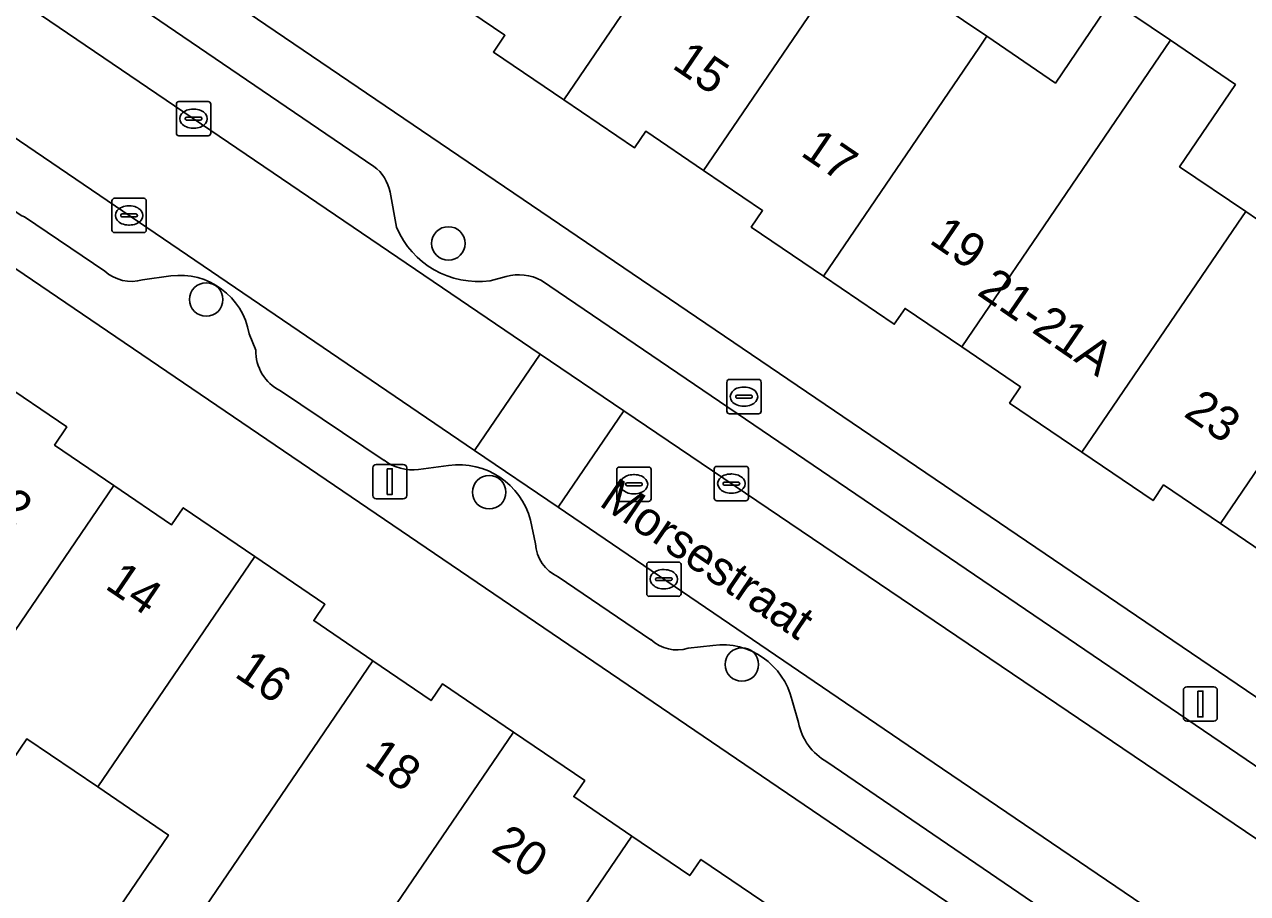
# Model space of a CAD drawing. Extents: x 159279 to 160377, y 384531 to 385888.
# Drawn here: x 159870.14 to 159905.8, y 384790.68 to 384816.01 of the extents above; entities that cross this region are included whole.
import ezdxf

# ---------------------------------------------------------------- set-up
doc = ezdxf.new("R2010")
doc.units = 0
for name, color, linetype in [('IMGEO_Boom', 7, 'Continuous'), ('IMGEO_Brandkraan', 7, 'Continuous'), ('IMGEO_Erf', 7, 'Continuous'), ('IMGEO_Kolk', 7, 'Continuous'), ('IMGEO_Lichtmast', 7, 'Continuous'), ('IMGEO_Openbare_ruimte_label', 7, 'Continuous'), ('IMGEO_Pand', 7, 'Continuous'), ('IMGEO_Pand_nummerreeks', 7, 'Continuous'), ('IMGEO_Parkeervlak_open', 7, 'Continuous'), ('IMGEO_Rijbaan_lokaal_open', 7, 'Continuous'), ('IMGEO_Rioolput', 7, 'Continuous'), ('IMGEO_Voetpad_open', 7, 'Continuous')]:
    doc.layers.add(name, color=color, linetype=linetype)

msp = doc.modelspace()

# ---------------------------------------------------------------- linework, layer by layer
at = {"layer": 'IMGEO_Boom'}
for centre in [(159882.498, 384809.63), (159875.436, 384807.995), (159883.686, 384802.377), (159891.055, 384797.353)]:
    msp.add_circle(centre, 0.489, dxfattribs=at)
at = {"layer": 'IMGEO_Brandkraan'}
for p, q in [((159890.616, 384804.738), (159890.616, 384805.59)), ((159890.691, 384805.664), (159891.543, 384805.664)), ((159891.617, 384805.59), (159891.617, 384804.738)), ((159890.875, 384805.158), (159890.875, 384805.17)), ((159891.313, 384805.121), (159890.915, 384805.121)), ((159890.918, 384805.207), (159891.316, 384805.207)), ((159891.104, 384805.444), (159891.129, 384805.444)), ((159891.359, 384805.17), (159891.359, 384805.158)), ((159891.127, 384804.884), (159891.102, 384804.884)), ((159891.543, 384804.664), (159890.691, 384804.664))]:
    msp.add_line(p, q, dxfattribs=at)
for points in [[(159890.616, 384804.738), (159890.616, 384805.59)], [(159890.691, 384805.664), (159891.543, 384805.664)], [(159891.617, 384805.59), (159891.617, 384804.738)], [(159891.543, 384804.664), (159890.691, 384804.664)]]:
    msp.add_lwpolyline(points, dxfattribs=at)
for centre, radius, start, end in [((159890.693, 384805.588), 0.0765, 91.552, 178.448), ((159890.693, 384805.588), 0.0765, 91.552, 178.448), ((159891.541, 384805.588), 0.0765, 1.552, 88.448), ((159891.541, 384805.588), 0.0765, 1.552, 88.448), ((159890.915, 384805.167), 0.0403, 85.8775, 175.7526), ((159890.912, 384805.157), 0.0366, 178.938, 274.7102), ((159891.316, 384805.164), 0.043, 264.8664, 352.4533), ((159891.32, 384805.169), 0.0386, 1.7309, 96.639), ((159890.693, 384804.74), 0.0765, 181.552, 268.448), ((159890.693, 384804.74), 0.0765, 181.552, 268.448), ((159891.541, 384804.74), 0.0765, 271.552, 358.448), ((159891.541, 384804.74), 0.0765, 271.552, 358.448)]:
    msp.add_arc(centre, radius, start, end, dxfattribs=at)
for centre, major_axis, ratio, start_param, end_param in [((159891.103, 384805.164), (-0.387, 0.002), 0.722429, 4.712389, 7.853982), ((159891.128, 384805.164), (-0.39, 0.002), 0.717154, 1.570796, 4.712389)]:
    msp.add_ellipse(centre, major_axis=major_axis, ratio=ratio, start_param=start_param, end_param=end_param, dxfattribs=at)
at = {"layer": 'IMGEO_Erf'}
for points in [[(159857.677, 384829.243), (159933.27, 384777.928)], [(159927.578, 384769.66), (159852.026, 384821.042)], [(159896.183, 384817.035), (159898.193, 384815.669), (159900.198, 384814.306), (159901.837, 384816.717), (159903.548, 384815.554), (159905.445, 384814.264), (159903.817, 384811.868), (159905.747, 384810.557), (159907.451, 384809.398)], [(159906.712, 384800.308), (159905.008, 384801.466), (159903.352, 384802.591), (159903.043, 384802.135), (159900.968, 384803.545), (159898.862, 384804.977), (159899.182, 384805.446), (159897.464, 384806.614), (159895.813, 384807.736), (159895.498, 384807.273), (159893.434, 384808.676), (159891.329, 384810.106), (159891.657, 384810.588), (159889.939, 384811.756), (159888.252, 384812.903), (159887.922, 384812.417), (159885.866, 384813.814), (159883.812, 384815.21), (159884.145, 384815.699), (159882.458, 384816.846)], [(159869.335, 384805.667), (159871.372, 384804.279), (159871.013, 384803.752), (159872.744, 384802.573), (159874.429, 384801.426), (159874.768, 384801.924), (159876.853, 384800.504), (159878.898, 384799.112), (159878.571, 384798.632), (159880.295, 384797.458), (159881.995, 384796.3), (159882.33, 384796.792), (159884.398, 384795.384), (159886.472, 384793.971), (159886.152, 384793.501), (159887.847, 384792.347), (159889.535, 384791.197), (159889.859, 384791.672), (159891.94, 384790.255)], [(159871.515, 384788.242), (159874.333, 384792.38), (159872.274, 384793.782), (159870.211, 384795.187), (159867.425, 384791.096)]]:
    msp.add_lwpolyline(points, dxfattribs=at)
at = {"layer": 'IMGEO_Kolk'}
for p, q in [((159874.567, 384812.842), (159874.567, 384813.694)), ((159874.642, 384813.768), (159875.494, 384813.768)), ((159875.568, 384813.694), (159875.568, 384812.842)), ((159874.869, 384813.311), (159875.267, 384813.311)), ((159875.055, 384813.548), (159875.08, 384813.548)), ((159874.826, 384813.262), (159874.826, 384813.274)), ((159875.264, 384813.225), (159874.866, 384813.225)), ((159875.078, 384812.988), (159875.053, 384812.988)), ((159875.31, 384813.274), (159875.31, 384813.262)), ((159875.494, 384812.768), (159874.642, 384812.768)), ((159872.688, 384810.02), (159872.688, 384810.872)), ((159872.763, 384810.946), (159873.615, 384810.946)), ((159873.689, 384810.872), (159873.689, 384810.02)), ((159872.99, 384810.489), (159873.388, 384810.489)), ((159873.176, 384810.726), (159873.201, 384810.726)), ((159872.947, 384810.44), (159872.947, 384810.452)), ((159873.385, 384810.403), (159872.987, 384810.403)), ((159873.199, 384810.166), (159873.174, 384810.166)), ((159873.431, 384810.452), (159873.431, 384810.44)), ((159873.615, 384809.946), (159872.763, 384809.946)), ((159890.248, 384802.202), (159890.248, 384803.054)), ((159890.323, 384803.128), (159891.175, 384803.128)), ((159891.249, 384803.054), (159891.249, 384802.202)), ((159890.507, 384802.622), (159890.507, 384802.634)), ((159890.55, 384802.671), (159890.948, 384802.671)), ((159890.736, 384802.908), (159890.761, 384802.908)), ((159890.991, 384802.634), (159890.991, 384802.622)), ((159890.945, 384802.585), (159890.547, 384802.585)), ((159890.759, 384802.348), (159890.734, 384802.348)), ((159891.175, 384802.128), (159890.323, 384802.128)), ((159888.28, 384799.415), (159888.28, 384800.267)), ((159888.355, 384800.341), (159889.207, 384800.341)), ((159888.768, 384800.121), (159888.793, 384800.121)), ((159889.281, 384800.267), (159889.281, 384799.415)), ((159888.539, 384799.835), (159888.539, 384799.847)), ((159888.977, 384799.798), (159888.579, 384799.798)), ((159888.582, 384799.884), (159888.98, 384799.884)), ((159889.023, 384799.847), (159889.023, 384799.835)), ((159888.791, 384799.561), (159888.766, 384799.561)), ((159889.207, 384799.341), (159888.355, 384799.341))]:
    msp.add_line(p, q, dxfattribs=at)
for points in [[(159874.567, 384812.842), (159874.567, 384813.694)], [(159874.642, 384813.768), (159875.494, 384813.768)], [(159875.568, 384813.694), (159875.568, 384812.842)], [(159875.494, 384812.768), (159874.642, 384812.768)], [(159872.688, 384810.02), (159872.688, 384810.872)], [(159872.763, 384810.946), (159873.615, 384810.946)], [(159873.689, 384810.872), (159873.689, 384810.02)], [(159873.615, 384809.946), (159872.763, 384809.946)], [(159890.248, 384802.202), (159890.248, 384803.054)], [(159890.323, 384803.128), (159891.175, 384803.128)], [(159891.249, 384803.054), (159891.249, 384802.202)], [(159891.175, 384802.128), (159890.323, 384802.128)], [(159888.28, 384799.415), (159888.28, 384800.267)], [(159888.355, 384800.341), (159889.207, 384800.341)], [(159889.281, 384800.267), (159889.281, 384799.415)], [(159889.207, 384799.341), (159888.355, 384799.341)]]:
    msp.add_lwpolyline(points, dxfattribs=at)
for centre, radius, start, end in [((159874.644, 384813.692), 0.0765, 91.552, 178.448), ((159874.644, 384813.692), 0.0765, 91.552, 178.448), ((159875.492, 384813.692), 0.0765, 1.552, 88.448), ((159875.492, 384813.692), 0.0765, 1.552, 88.448), ((159874.866, 384813.271), 0.0403, 85.8775, 175.7526), ((159875.271, 384813.273), 0.0386, 1.7309, 96.639), ((159874.863, 384813.261), 0.0366, 178.938, 274.7102), ((159875.267, 384813.268), 0.043, 264.8664, 352.4533), ((159874.644, 384812.844), 0.0765, 181.552, 268.448), ((159874.644, 384812.844), 0.0765, 181.552, 268.448), ((159875.492, 384812.844), 0.0765, 271.552, 358.448), ((159875.492, 384812.844), 0.0765, 271.552, 358.448), ((159872.765, 384810.87), 0.0765, 91.552, 178.448), ((159872.765, 384810.87), 0.0765, 91.552, 178.448), ((159873.613, 384810.87), 0.0765, 1.552, 88.448), ((159873.613, 384810.87), 0.0765, 1.552, 88.448), ((159872.987, 384810.449), 0.0403, 85.8775, 175.7526), ((159873.392, 384810.451), 0.0386, 1.7309, 96.639), ((159872.984, 384810.439), 0.0366, 178.938, 274.7102), ((159873.388, 384810.446), 0.043, 264.8664, 352.4533), ((159872.765, 384810.022), 0.0765, 181.552, 268.448), ((159872.765, 384810.022), 0.0765, 181.552, 268.448), ((159873.613, 384810.022), 0.0765, 271.552, 358.448), ((159873.613, 384810.022), 0.0765, 271.552, 358.448), ((159890.325, 384803.052), 0.0765, 91.552, 178.448), ((159890.325, 384803.052), 0.0765, 91.552, 178.448), ((159891.173, 384803.052), 0.0765, 1.552, 88.448), ((159891.173, 384803.052), 0.0765, 1.552, 88.448), ((159890.547, 384802.631), 0.0403, 85.8775, 175.7526), ((159890.544, 384802.621), 0.0366, 178.938, 274.7102), ((159890.948, 384802.628), 0.043, 264.8664, 352.4533), ((159890.952, 384802.633), 0.0386, 1.7309, 96.639), ((159890.325, 384802.204), 0.0765, 181.552, 268.448), ((159890.325, 384802.204), 0.0765, 181.552, 268.448), ((159891.173, 384802.204), 0.0765, 271.552, 358.448), ((159891.173, 384802.204), 0.0765, 271.552, 358.448), ((159888.357, 384800.265), 0.0765, 91.552, 178.448), ((159888.357, 384800.265), 0.0765, 91.552, 178.448), ((159889.205, 384800.265), 0.0765, 1.552, 88.448), ((159889.205, 384800.265), 0.0765, 1.552, 88.448), ((159888.579, 384799.844), 0.0403, 85.8775, 175.7526), ((159888.576, 384799.834), 0.0366, 178.938, 274.7102), ((159888.98, 384799.841), 0.043, 264.8664, 352.4533), ((159888.984, 384799.846), 0.0386, 1.7309, 96.639), ((159888.357, 384799.417), 0.0765, 181.552, 268.448), ((159888.357, 384799.417), 0.0765, 181.552, 268.448), ((159889.205, 384799.417), 0.0765, 271.552, 358.448), ((159889.205, 384799.417), 0.0765, 271.552, 358.448)]:
    msp.add_arc(centre, radius, start, end, dxfattribs=at)
for centre, major_axis, ratio, start_param, end_param in [((159875.054, 384813.268), (-0.387, 0.002), 0.722429, 4.712389, 7.853982), ((159875.079, 384813.268), (-0.39, 0.002), 0.717154, 1.570796, 4.712389), ((159873.175, 384810.446), (-0.387, 0.002), 0.722429, 4.712389, 7.853982), ((159873.2, 384810.446), (-0.39, 0.002), 0.717154, 1.570796, 4.712389), ((159890.735, 384802.628), (-0.387, 0.002), 0.722429, 4.712389, 7.853982), ((159890.76, 384802.628), (-0.39, 0.002), 0.717154, 1.570796, 4.712389), ((159888.767, 384799.841), (-0.387, 0.002), 0.722429, 4.712389, 7.853982), ((159888.792, 384799.841), (-0.39, 0.002), 0.717154, 1.570796, 4.712389)]:
    msp.add_ellipse(centre, major_axis=major_axis, ratio=ratio, start_param=start_param, end_param=end_param, dxfattribs=at)
at = {"layer": 'IMGEO_Lichtmast'}
for p, q in [((159880.293, 384802.285), (159880.293, 384803.085)), ((159880.293, 384803.085), (159880.293, 384802.285)), ((159880.393, 384803.185), (159881.183, 384803.185)), ((159881.183, 384803.185), (159880.393, 384803.185)), ((159881.283, 384803.085), (159881.283, 384802.285)), ((159881.283, 384802.285), (159881.283, 384803.085)), ((159881.183, 384802.185), (159880.393, 384802.185)), ((159880.393, 384802.185), (159881.183, 384802.185)), ((159903.927, 384795.801), (159903.927, 384796.601)), ((159903.927, 384796.601), (159903.927, 384795.801)), ((159904.027, 384796.701), (159904.817, 384796.701)), ((159904.817, 384796.701), (159904.027, 384796.701)), ((159904.917, 384796.601), (159904.917, 384795.801)), ((159904.917, 384795.801), (159904.917, 384796.601)), ((159904.817, 384795.701), (159904.027, 384795.701)), ((159904.027, 384795.701), (159904.817, 384795.701))]:
    msp.add_line(p, q, dxfattribs=at)
for points in [[(159880.713, 384803.06), (159880.863, 384803.06), (159880.863, 384802.31), (159880.713, 384802.31), (159880.713, 384803.06)], [(159904.347, 384796.576), (159904.497, 384796.576), (159904.497, 384795.826), (159904.347, 384795.826), (159904.347, 384796.576)]]:
    msp.add_lwpolyline(points, dxfattribs=at)
for centre, start, end in [((159880.393, 384803.085), 90, 180), ((159880.393, 384803.085), 90, 180), ((159881.183, 384803.085), 0, 90), ((159881.183, 384803.085), 360, 90), ((159880.393, 384802.285), 180, 270), ((159880.393, 384802.285), 180, 270), ((159881.183, 384802.285), 270, 0), ((159881.183, 384802.285), 270, 0), ((159904.027, 384796.601), 90, 180), ((159904.027, 384796.601), 90, 180), ((159904.817, 384796.601), 0, 90), ((159904.817, 384796.601), 360, 90), ((159904.027, 384795.801), 180, 270), ((159904.027, 384795.801), 180, 270), ((159904.817, 384795.801), 270, 0), ((159904.817, 384795.801), 270, 0)]:
    msp.add_arc(centre, 0.1, start, end, dxfattribs=at)
at = {"layer": 'IMGEO_Pand'}
for points in [[(159892.175, 384823.123), (159890.141, 384824.506), (159893.232, 384829.055), (159893.069, 384829.166), (159891.286, 384830.378), (159891.221, 384830.28), (159889.322, 384827.386), (159889.51, 384827.262), (159888.511, 384825.74), (159882.458, 384816.846), (159884.145, 384815.699), (159883.812, 384815.21), (159885.866, 384813.814), (159890.417, 384820.5), (159890.647, 384820.837)], [(159896.035, 384820.715), (159896.794, 384821.831), (159897.628, 384823.101), (159895.864, 384824.258), (159894.387, 384822.007), (159892.343, 384823.374), (159892.175, 384823.123), (159890.647, 384820.837), (159890.417, 384820.5), (159885.866, 384813.814), (159887.922, 384812.417), (159888.252, 384812.903), (159889.939, 384811.756)], [(159897.846, 384819.483), (159898.605, 384820.601), (159896.794, 384821.831), (159896.035, 384820.715), (159889.939, 384811.756), (159891.657, 384810.588), (159891.329, 384810.106), (159893.434, 384808.676), (159897.979, 384815.354), (159898.193, 384815.669), (159896.183, 384817.035)], [(159893.434, 384808.676), (159895.498, 384807.273), (159895.813, 384807.736), (159897.464, 384806.614), (159903.548, 384815.554), (159901.837, 384816.717), (159900.198, 384814.306), (159898.193, 384815.669), (159897.979, 384815.354)], [(159905.514, 384810.225), (159905.747, 384810.557), (159903.817, 384811.868), (159905.445, 384814.264), (159903.548, 384815.554), (159897.464, 384806.614), (159899.182, 384805.446), (159898.862, 384804.977), (159900.968, 384803.545)], [(159911.113, 384810.437), (159911.848, 384811.527), (159913.079, 384813.295), (159911.041, 384814.68), (159907.451, 384809.398), (159905.747, 384810.557), (159905.514, 384810.225), (159900.968, 384803.545), (159903.043, 384802.135), (159903.352, 384802.591), (159905.008, 384801.466)], [(159911.199, 384806.878), (159912.827, 384809.272), (159915.083, 384812.59), (159913.39, 384813.742), (159913.079, 384813.295), (159911.848, 384811.527), (159911.113, 384810.437), (159905.008, 384801.466), (159906.712, 384800.308), (159906.391, 384799.836), (159908.595, 384798.339), (159913.148, 384805.031), (159913.39, 384805.388)], [(159872.744, 384802.573), (159871.013, 384803.752), (159871.372, 384804.279), (159869.335, 384805.667), (159864.738, 384798.918), (159866.866, 384797.469), (159864.078, 384793.375), (159865.719, 384792.257)], [(159865.719, 384792.257), (159867.425, 384791.096), (159870.211, 384795.187), (159872.274, 384793.782), (159876.853, 384800.504), (159874.768, 384801.924), (159874.429, 384801.426), (159872.744, 384802.573)], [(159880.295, 384797.458), (159878.571, 384798.632), (159878.898, 384799.112), (159876.853, 384800.504), (159872.274, 384793.782), (159874.333, 384792.38), (159871.515, 384788.242), (159873.093, 384787.167), (159873.225, 384787.078)], [(159884.398, 384795.384), (159882.33, 384796.792), (159881.995, 384796.3), (159880.295, 384797.458), (159873.225, 384787.078), (159874.799, 384786.006), (159875.897, 384787.618), (159878.115, 384786.14), (159879.822, 384788.664)], [(159887.847, 384792.347), (159886.152, 384793.501), (159886.472, 384793.971), (159884.398, 384795.384), (159879.822, 384788.664), (159878.115, 384786.14), (159880.107, 384784.813), (159879.015, 384783.209), (159880.797, 384781.995)], [(159891.94, 384790.255), (159889.859, 384791.672), (159889.535, 384791.197), (159887.847, 384792.347), (159880.797, 384781.995), (159882.488, 384780.844), (159883.44, 384782.242), (159885.518, 384780.826), (159887.372, 384783.548)]]:
    msp.add_lwpolyline(points, close=True, dxfattribs=at)
at = {"layer": 'IMGEO_Parkeervlak_open'}
for points in [[(159841.061, 384836.342), (159869.05, 384817.352), (159885.17, 384806.406), (159887.611, 384804.749), (159908.324, 384790.738), (159926.959, 384778.09), (159945.396, 384765.37), (159945.552, 384765.562)], [(159943.334, 384762.401), (159943.479, 384762.606), (159926.868, 384773.971), (159896.121, 384794.85), (159885.702, 384801.937), (159883.263, 384803.596), (159866.73, 384814.841), (159839.216, 384833.593)], [(159880.327, 384811.876), (159859.008, 384826.382)], [(159880.985, 384810.1), (159880.796, 384811.121)], [(159870.137, 384810.402), (159872.483, 384808.821)], [(159873.579, 384808.57), (159874.403, 384808.682)], [(159884.181, 384808.664), (159883.713, 384808.543)], [(159918.388, 384786.002), (159885.211, 384808.551)], [(159876.686, 384806.999), (159876.884, 384806.519)], [(159877.598, 384805.335), (159880.623, 384803.306)], [(159881.63, 384803.04), (159882.505, 384803.154)], [(159884.889, 384801.56), (159885.038, 384800.876)], [(159885.699, 384799.907), (159888.404, 384798.077)], [(159889.487, 384797.825), (159890.209, 384797.911)], [(159892.517, 384796.304), (159892.704, 384795.659)], [(159893.533, 384794.514), (159901.391, 384789.147)]]:
    msp.add_lwpolyline(points, dxfattribs=at)
for centre, radius, start, end in [((159879.592, 384810.896), 1.225, 10.5702, 53.1262), ((159870.521, 384811.357), 1.029, 172.7943, 248.086), ((159883.367, 384811.106), 2.586, 202.8873, 277.6818), ((159873.254, 384809.67), 1.147, 227.7469, 286.4548), ((159874.671, 384806.656), 2.044, 9.6619, 97.5438), ((159884.557, 384807.338), 1.378, 61.6553, 105.8231), ((159878.161, 384806.482), 1.277, 178.328, 243.8554), ((159881.459, 384804.432), 1.402, 233.4008, 277.0056), ((159882.805, 384801.023), 2.152, 14.4562, 98.0085), ((159886.188, 384800.95), 1.152, 183.6976, 244.9018), ((159889.169, 384798.912), 1.132, 227.4929, 286.3093), ((159890.474, 384795.831), 2.097, 13.04, 97.2631), ((159894.371, 384795.993), 1.7, 191.3347, 240.4757)]:
    msp.add_arc(centre, radius, start, end, dxfattribs=at)
at = {"layer": 'IMGEO_Rijbaan_lokaal_open'}
for points in [[(159885.17, 384806.406), (159869.05, 384817.352), (159841.061, 384836.342), (159840.702, 384836.586), (159838.838, 384833.851), (159839.216, 384833.593), (159866.73, 384814.841), (159883.263, 384803.596)], [(159885.17, 384806.406), (159883.263, 384803.596), (159885.702, 384801.937), (159887.611, 384804.749)], [(159926.959, 384778.09), (159908.324, 384790.738), (159887.611, 384804.749), (159885.702, 384801.937), (159896.121, 384794.85), (159926.868, 384773.971), (159943.479, 384762.606), (159945.396, 384765.37)]]:
    msp.add_lwpolyline(points, close=True, dxfattribs=at)
at = {"layer": 'IMGEO_Rioolput'}
for p, q in [((159887.407, 384802.184), (159887.407, 384803.036)), ((159887.482, 384803.11), (159888.334, 384803.11)), ((159888.408, 384803.036), (159888.408, 384802.184)), ((159887.666, 384802.604), (159887.666, 384802.616)), ((159887.709, 384802.653), (159888.107, 384802.653)), ((159887.895, 384802.89), (159887.92, 384802.89)), ((159888.15, 384802.616), (159888.15, 384802.604)), ((159888.104, 384802.567), (159887.706, 384802.567)), ((159887.918, 384802.33), (159887.893, 384802.33)), ((159888.334, 384802.11), (159887.482, 384802.11))]:
    msp.add_line(p, q, dxfattribs=at)
for points in [[(159887.407, 384802.184), (159887.407, 384803.036)], [(159887.482, 384803.11), (159888.334, 384803.11)], [(159888.408, 384803.036), (159888.408, 384802.184)], [(159888.334, 384802.11), (159887.482, 384802.11)]]:
    msp.add_lwpolyline(points, dxfattribs=at)
for centre, radius, start, end in [((159887.484, 384803.034), 0.0765, 91.552, 178.448), ((159887.484, 384803.034), 0.0765, 91.552, 178.448), ((159888.332, 384803.034), 0.0765, 1.552, 88.448), ((159888.332, 384803.034), 0.0765, 1.552, 88.448), ((159887.706, 384802.613), 0.0403, 85.8775, 175.7526), ((159888.111, 384802.615), 0.0386, 1.7309, 96.639), ((159887.703, 384802.603), 0.0366, 178.938, 274.7102), ((159888.107, 384802.61), 0.043, 264.8664, 352.4533), ((159887.484, 384802.186), 0.0765, 181.552, 268.448), ((159887.484, 384802.186), 0.0765, 181.552, 268.448), ((159888.332, 384802.186), 0.0765, 271.552, 358.448), ((159888.332, 384802.186), 0.0765, 271.552, 358.448)]:
    msp.add_arc(centre, radius, start, end, dxfattribs=at)
for centre, major_axis, ratio, start_param, end_param in [((159887.894, 384802.61), (-0.387, 0.002), 0.722429, 4.712389, 7.853982), ((159887.919, 384802.61), (-0.39, 0.002), 0.717154, 1.570796, 4.712389)]:
    msp.add_ellipse(centre, major_axis=major_axis, ratio=ratio, start_param=start_param, end_param=end_param, dxfattribs=at)
at = {"layer": 'IMGEO_Voetpad_open'}
for points in [[(159839.216, 384833.593), (159838.838, 384833.851), (159838.334, 384834.194), (159838.015, 384834.391), (159837.68, 384834.559), (159835.991, 384831.945), (159843.603, 384826.792), (159848.594, 384823.395), (159851.246, 384821.574), (159852.026, 384821.042), (159927.578, 384769.66), (159928.216, 384769.226), (159928.533, 384769.015), (159941.948, 384760.067), (159943.396, 384762.244), (159943.334, 384762.401)], [(159945.552, 384765.562), (159947.447, 384768.384), (159942.761, 384771.531), (159933.683, 384777.648), (159933.27, 384777.928), (159857.677, 384829.243)], [(159859.008, 384826.382), (159880.327, 384811.876)], [(159880.796, 384811.121), (159880.985, 384810.1)], [(159872.483, 384808.821), (159870.137, 384810.402)], [(159874.403, 384808.682), (159873.579, 384808.57)], [(159883.713, 384808.543), (159884.181, 384808.664)], [(159885.211, 384808.551), (159918.388, 384786.002)], [(159876.884, 384806.519), (159876.686, 384806.999)], [(159880.623, 384803.306), (159877.598, 384805.335)], [(159882.505, 384803.154), (159881.63, 384803.04)], [(159885.038, 384800.876), (159884.889, 384801.56)], [(159888.404, 384798.077), (159885.699, 384799.907)], [(159890.209, 384797.911), (159889.487, 384797.825)], [(159892.704, 384795.659), (159892.517, 384796.304)], [(159901.391, 384789.147), (159893.533, 384794.514)]]:
    msp.add_lwpolyline(points, dxfattribs=at)
for centre, radius, start, end in [((159879.592, 384810.896), 1.225, 10.5702, 53.1262), ((159870.521, 384811.357), 1.029, 172.7943, 248.086), ((159883.367, 384811.106), 2.586, 202.8873, 277.6818), ((159873.254, 384809.67), 1.147, 227.7469, 286.4548), ((159874.671, 384806.656), 2.044, 9.6619, 97.5438), ((159884.557, 384807.338), 1.378, 61.6553, 105.8231), ((159878.161, 384806.482), 1.277, 178.328, 243.8554), ((159881.459, 384804.432), 1.402, 233.4008, 277.0056), ((159882.805, 384801.023), 2.152, 14.4562, 98.0085), ((159886.188, 384800.95), 1.152, 183.6976, 244.9018), ((159889.169, 384798.912), 1.132, 227.4929, 286.3093), ((159890.474, 384795.831), 2.097, 13.04, 97.2631), ((159894.371, 384795.993), 1.7, 191.3347, 240.4757)]:
    msp.add_arc(centre, radius, start, end, dxfattribs=at)

# ---------------------------------------------------------------- texts
at = {"layer": 'IMGEO_Openbare_ruimte_label'}
msp.add_text('Morsestraat', height=1, rotation=325.8014, dxfattribs=at).set_placement((159886.856, 384802.01))
at = {"layer": 'IMGEO_Pand_nummerreeks'}
for s, rotation, p in [('15', 325.76, (159888.985, 384814.766)), ('17', 325.759, (159892.733, 384812.214)), ('19', 325.759, (159896.482, 384809.663)), ('21-21A', 325.5939, (159897.88, 384808.156)), ('23', 325.76, (159903.904, 384804.611)), ('12', 325.7429, (159868.673, 384802.165)), ('14', 325.7429, (159872.451, 384799.591)), ('16', 325.7429, (159876.227, 384797.02)), ('18', 325.7429, (159880.006, 384794.446)), ('20', 325.7429, (159883.706, 384791.926))]:
    msp.add_text(s, height=1, rotation=rotation, dxfattribs=at).set_placement(p)

doc.saveas('drawing.dxf')
